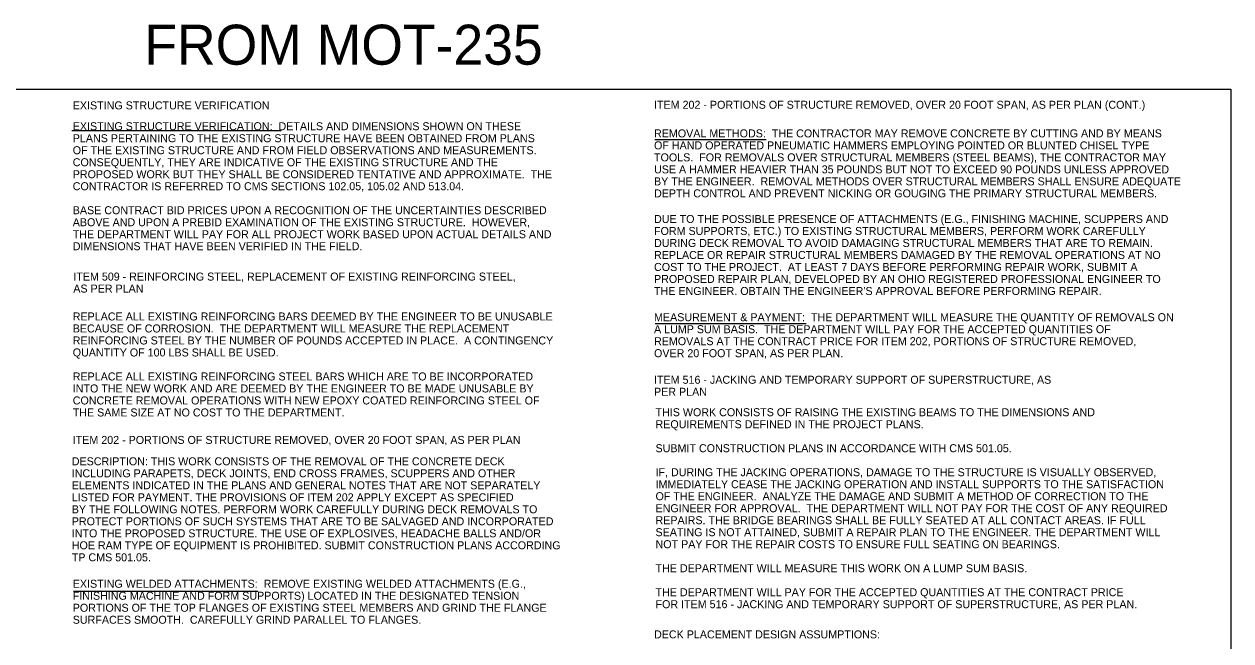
# Model space of a CAD drawing. Extents: x -10.6 to 33.4, y -28.4 to 21.5.
# Drawn here: x 11.39 to 32.5, y -17.08 to -6.29 of the extents above; entities that cross this region are included whole.
import ezdxf

# ---------------------------------------------------------------- set-up
doc = ezdxf.new("R2010")
doc.units = 0
for name, color, linetype in [('BR_P_Gen_Text', 7, 'Continuous'), ('Default', 7, 'Continuous'), ('SC_Scratch1', 7, 'Continuous')]:
    doc.layers.add(name, color=color, linetype=linetype)

msp = doc.modelspace()

# ---------------------------------------------------------------- linework, layer by layer
at = {"layer": 'BR_P_Gen_Text'}
for p, q in [((12.227, -8.155), (15.889, -8.155)), ((22.426, -8.311), (24.372, -8.311)), ((22.427, -11.532), (25.074, -11.532)), ((12.257, -16.214), (15.48, -16.214))]:
    msp.add_line(p, q, dxfattribs=at)
at = {"layer": 'SC_Scratch1'}
msp.add_lwpolyline([(2, -7.427), (32.5, -7.427), (32.5, -28.427), (2, -28.427)], close=True, dxfattribs=at)

# ---------------------------------------------------------------- texts
at = {"layer": 'BR_P_Gen_Text'}
for s, p in [('EXISTING STRUCTURE VERIFICATION', (12.242, -7.783)), ('ITEM 202 - PORTIONS OF STRUCTURE REMOVED, OVER 20 FOOT SPAN, AS PER PLAN (CONT.)', (22.41, -7.772)), ('EXISTING STRUCTURE VERIFICATION:  DETAILS AND DIMENSIONS SHOWN ON THESE', (12.242, -8.148)), ('PLANS PERTAINING TO THE EXISTING STRUCTURE HAVE BEEN OBTAINED FROM PLANS', (12.242, -8.358)), ('OF THE EXISTING STRUCTURE AND FROM FIELD OBSERVATIONS AND MEASUREMENTS.', (12.242, -8.568)), ('CONSEQUENTLY, THEY ARE INDICATIVE OF THE EXISTING STRUCTURE AND THE', (12.242, -8.778)), ('PROPOSED WORK BUT THEY SHALL BE CONSIDERED TENTATIVE AND APPROXIMATE.  THE', (12.242, -8.988)), ('CONTRACTOR IS REFERRED TO CMS SECTIONS 102.05, 105.02 AND 513.04.', (12.242, -9.198)), ('BASE CONTRACT BID PRICES UPON A RECOGNITION OF THE UNCERTAINTIES DESCRIBED', (12.242, -9.618)), ('ABOVE AND UPON A PREBID EXAMINATION OF THE EXISTING STRUCTURE.  HOWEVER,', (12.242, -9.828)), ('THE DEPARTMENT WILL PAY FOR ALL PROJECT WORK BASED UPON ACTUAL DETAILS AND', (12.242, -10.038)), ('DIMENSIONS THAT HAVE BEEN VERIFIED IN THE FIELD.', (12.242, -10.248)), ('ITEM 509 - REINFORCING STEEL, REPLACEMENT OF EXISTING REINFORCING STEEL,', (12.252, -10.779)), ('AS PER PLAN', (12.252, -10.989)), ('REPLACE ALL EXISTING REINFORCING BARS DEEMED BY THE ENGINEER TO BE UNUSABLE', (12.242, -11.477)), ('MEASUREMENT & PAYMENT:  THE DEPARTMENT WILL MEASURE THE QUANTITY OF REMOVALS ON ', (22.41, -11.49)), ('BECAUSE OF CORROSION.  THE DEPARTMENT WILL MEASURE THE REPLACEMENT', (12.242, -11.687)), ('A LUMP SUM BASIS.  THE DEPARTMENT WILL PAY FOR THE ACCEPTED QUANTITIES OF ', (22.41, -11.7)), ('REINFORCING STEEL BY THE NUMBER OF POUNDS ACCEPTED IN PLACE.  A CONTINGENCY', (12.242, -11.897)), ('REMOVALS AT THE CONTRACT PRICE FOR ITEM 202, PORTIONS OF STRUCTURE REMOVED, ', (22.41, -11.91)), ('QUANTITY OF 100 LBS SHALL BE USED.', (12.242, -12.107)), ('OVER 20 FOOT SPAN, AS PER PLAN.', (22.41, -12.12)), ('REPLACE ALL EXISTING REINFORCING STEEL BARS WHICH ARE TO BE INCORPORATED', (12.242, -12.527)), ('INTO THE NEW WORK AND ARE DEEMED BY THE ENGINEER TO BE MADE UNUSABLE BY', (12.242, -12.737)), ('CONCRETE REMOVAL OPERATIONS WITH NEW EPOXY COATED REINFORCING STEEL OF', (12.242, -12.947)), ('THE SAME SIZE AT NO COST TO THE DEPARTMENT.', (12.242, -13.157)), ('THIS WORK CONSISTS OF RAISING THE EXISTING BEAMS TO THE DIMENSIONS AND ', (22.436, -13.153)), ('REQUIREMENTS DEFINED IN THE PROJECT PLANS.', (22.436, -13.363)), ('ITEM 202 - PORTIONS OF STRUCTURE REMOVED, OVER 20 FOOT SPAN, AS PER PLAN', (12.242, -13.638)), ('SUBMIT CONSTRUCTION PLANS IN ACCORDANCE WITH CMS 501.05.', (22.436, -13.783)), ('DESCRIPTION: THIS WORK CONSISTS OF THE REMOVAL OF THE CONCRETE DECK ', (12.225, -14.012)), ('INCLUDING PARAPETS, DECK JOINTS, END CROSS FRAMES, SCUPPERS AND OTHER ', (12.225, -14.222)), ('IF, DURING THE JACKING OPERATIONS, DAMAGE TO THE STRUCTURE IS VISUALLY OBSERVED,', (22.436, -14.203)), ('ELEMENTS INDICATED IN THE PLANS AND GENERAL NOTES THAT ARE NOT SEPARATELY ', (12.225, -14.432)), ('IMMEDIATELY CEASE THE JACKING OPERATION AND INSTALL SUPPORTS TO THE SATISFACTION', (22.436, -14.413)), ('LISTED FOR PAYMENT. THE PROVISIONS OF ITEM 202 APPLY EXCEPT AS SPECIFIED ', (12.225, -14.642)), ('OF THE ENGINEER.  ANALYZE THE DAMAGE AND SUBMIT A METHOD OF CORRECTION TO THE', (22.436, -14.623)), ('BY THE FOLLOWING NOTES. PERFORM WORK CAREFULLY DURING DECK REMOVALS TO ', (12.225, -14.852)), ('ENGINEER FOR APPROVAL.  THE DEPARTMENT WILL NOT PAY FOR THE COST OF ANY REQUIRED', (22.436, -14.833)), ('PROTECT PORTIONS OF SUCH SYSTEMS THAT ARE TO BE SALVAGED AND INCORPORATED', (12.225, -15.062)), ('REPAIRS. THE BRIDGE BEARINGS SHALL BE FULLY SEATED AT ALL CONTACT AREAS. IF FULL', (22.436, -15.043)), ('INTO THE PROPOSED STRUCTURE. THE USE OF EXPLOSIVES, HEADACHE BALLS AND/OR', (12.225, -15.272)), ('SEATING IS NOT ATTAINED, SUBMIT A REPAIR PLAN TO THE ENGINEER. THE DEPARTMENT WILL', (22.436, -15.253)), ('HOE RAM TYPE OF EQUIPMENT IS PROHIBITED. SUBMIT CONSTRUCTION PLANS ACCORDING', (12.225, -15.482)), ('NOT PAY FOR THE REPAIR COSTS TO ENSURE FULL SEATING ON BEARINGS.  ', (22.436, -15.463)), ('TP CMS 501.05.', (12.225, -15.692)), ('THE DEPARTMENT WILL MEASURE THIS WORK ON A LUMP SUM BASIS.', (22.436, -15.883)), ('THE DEPARTMENT WILL PAY FOR THE ACCEPTED QUANTITIES AT THE CONTRACT PRICE ', (22.436, -16.303)), ('FOR ITEM 516 - JACKING AND TEMPORARY SUPPORT OF SUPERSTRUCTURE, AS PER PLAN.', (22.436, -16.513))]:
    msp.add_text(s, height=0.14, dxfattribs=at).set_placement(p)
at = {"layer": 'Default'}
for s, p in [('REMOVAL METHODS:  THE CONTRACTOR MAY REMOVE CONCRETE BY CUTTING AND BY MEANS ', (22.41, -8.273)), ('OF HAND OPERATED PNEUMATIC HAMMERS EMPLOYING POINTED OR BLUNTED CHISEL TYPE ', (22.41, -8.483)), ('TOOLS.  FOR REMOVALS OVER STRUCTURAL MEMBERS (STEEL BEAMS), THE CONTRACTOR MAY ', (22.41, -8.693)), ('USE A HAMMER HEAVIER THAN 35 POUNDS BUT NOT TO EXCEED 90 POUNDS UNLESS APPROVED ', (22.41, -8.903)), ('BY THE ENGINEER.  REMOVAL METHODS OVER STRUCTURAL MEMBERS SHALL ENSURE ADEQUATE ', (22.41, -9.113)), ('DEPTH CONTROL AND PREVENT NICKING OR GOUGING THE PRIMARY STRUCTURAL MEMBERS. ', (22.41, -9.323)), ('DUE TO THE POSSIBLE PRESENCE OF ATTACHMENTS (E.G., FINISHING MACHINE, SCUPPERS AND ', (22.41, -9.771)), ('FORM SUPPORTS, ETC.) TO EXISTING STRUCTURAL MEMBERS, PERFORM WORK CAREFULLY ', (22.41, -9.981)), ('DURING DECK REMOVAL TO AVOID DAMAGING STRUCTURAL MEMBERS THAT ARE TO REMAIN.  ', (22.41, -10.191)), ('REPLACE OR REPAIR STRUCTURAL MEMBERS DAMAGED BY THE REMOVAL OPERATIONS AT NO ', (22.41, -10.401)), ('COST TO THE PROJECT.  AT LEAST 7 DAYS BEFORE PERFORMING REPAIR WORK, SUBMIT A ', (22.41, -10.611)), ('PROPOSED REPAIR PLAN, DEVELOPED BY AN OHIO REGISTERED PROFESSIONAL ENGINEER TO ', (22.41, -10.821)), ("THE ENGINEER. OBTAIN THE ENGINEER'S APPROVAL BEFORE PERFORMING REPAIR.", (22.41, -11.031)), ('ITEM 516 - JACKING AND TEMPORARY SUPPORT OF SUPERSTRUCTURE, AS', (22.41, -12.585)), ('PER PLAN', (22.41, -12.795)), ('EXISTING WELDED ATTACHMENTS:  REMOVE EXISTING WELDED ATTACHMENTS (E.G., ', (12.242, -16.155)), ('FINISHING MACHINE AND FORM SUPPORTS) LOCATED IN THE DESIGNATED TENSION ', (12.242, -16.365)), ('PORTIONS OF THE TOP FLANGES OF EXISTING STEEL MEMBERS AND GRIND THE FLANGE ', (12.242, -16.575)), ('SURFACES SMOOTH.  CAREFULLY GRIND PARALLEL TO FLANGES.', (12.242, -16.785)), ('DECK PLACEMENT DESIGN ASSUMPTIONS:', (22.41, -17.041))]:
    msp.add_text(s, height=0.14, dxfattribs=at).set_placement(p)
at = {"layer": 'SC_Scratch1'}
msp.add_text('FROM MOT-235', height=0.7, dxfattribs=at).set_placement((13.494, -7.001))

doc.saveas('drawing.dxf')
